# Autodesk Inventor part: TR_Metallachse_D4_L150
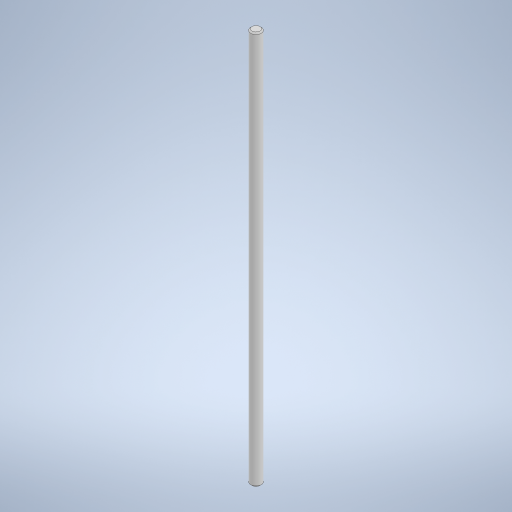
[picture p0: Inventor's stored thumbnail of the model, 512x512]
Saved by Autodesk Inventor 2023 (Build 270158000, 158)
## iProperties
Created: 2023-11
Part Number: TR_Metallachse_D4_L150
Material: Generisch
Document SubType Name: Modeling
Designer: Greiner
Density: 1 g/cm^3
Appearance: Vorgabe
Author: Greiner
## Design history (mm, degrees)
sketch "Skizze1"
  geometry: C1 r 2 at (0, 0); 1 further point
  constraints: 1 centre point, 1 coincident
  dimensions: "d0" = 4 diameter of C1 (= AchsDurchmesser)
extrude "Extrusion1" new body sketch "Skizze1" distance "d1" = 150; taper "d2" = 0 deg
chamfer "Fase1" distance "d3" = 0.5 (= AchsFase); stored, may be unused: second distance "d4" = 2, angle "d5" = 45 deg
node "Volumenkörper1"
other parameters: "Radius" = 2.075 [user parameter], "Fasen" = 0.5 [user parameter], "Dicke" = 0.8 [user parameter], "Breitloch" = 2 [user parameter], "Langloch" = 32 [user parameter], "AchteckUmkreis" = 6 [user parameter], "DAchsAufnahme" = 4.1 [user parameter], "AchsDurchmesser" = 4 [user parameter; used in 1 equation term], "AchsFase" = 0.5 [user parameter; used in 1 equation term]
